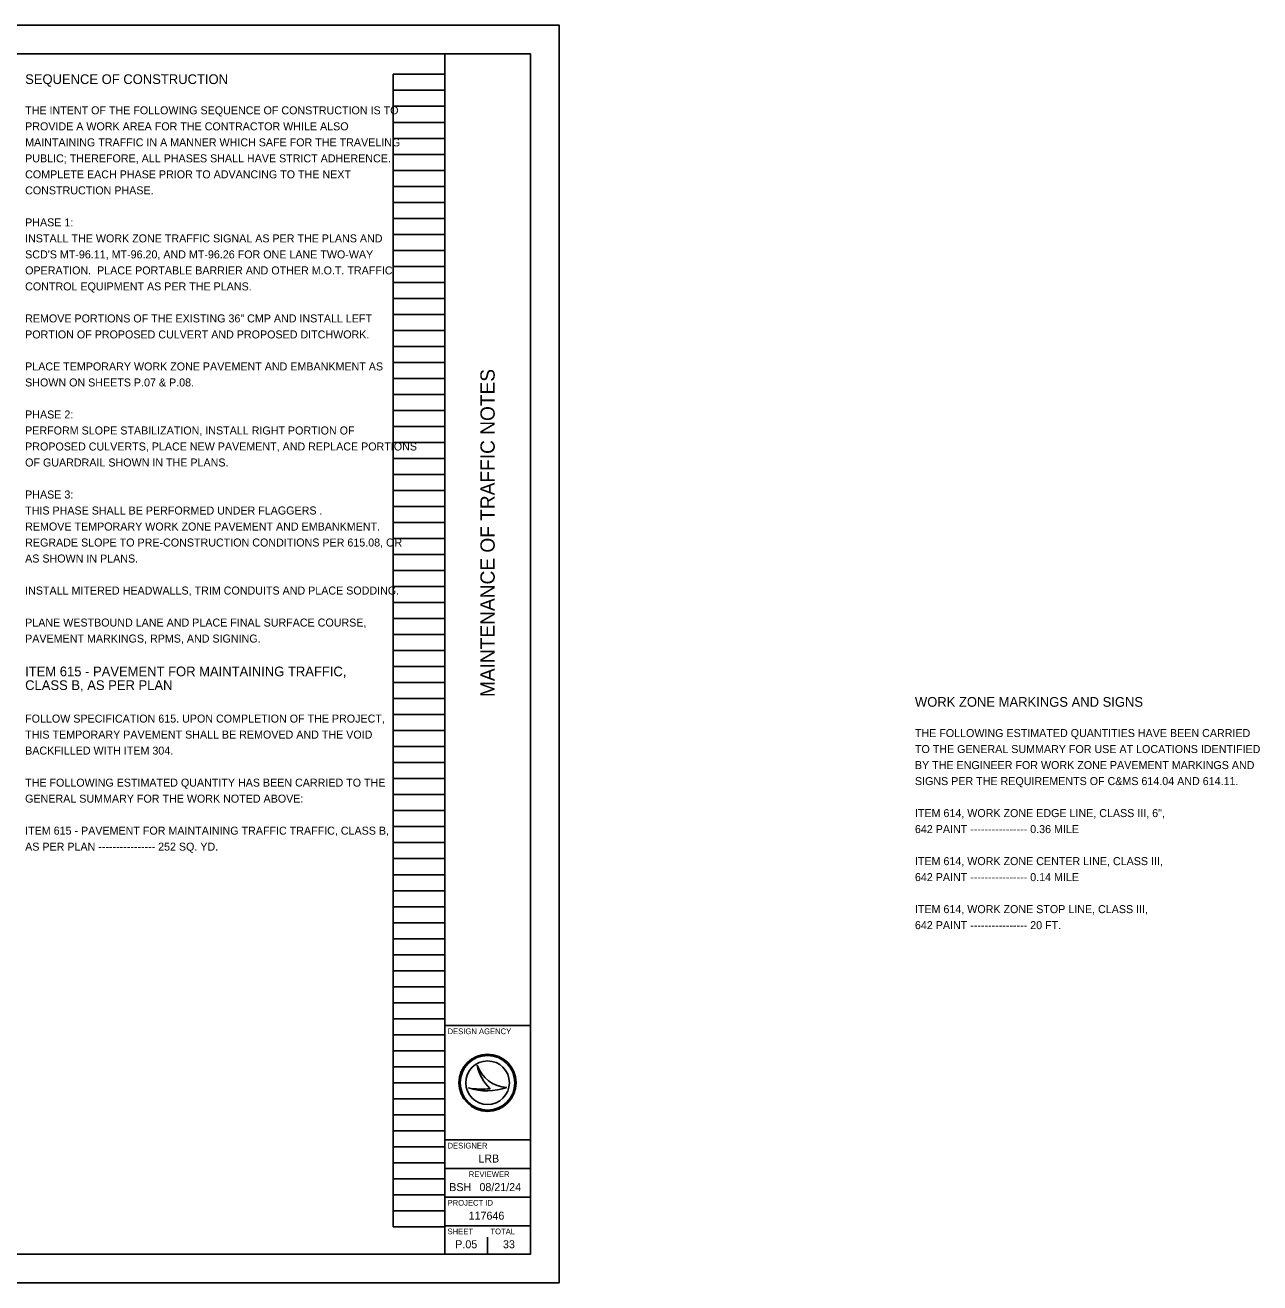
# Model space of a CAD drawing. Extents: x -7.5 to 46.3, y -5.1 to 34.9.
# Drawn here: x 24.66 to 46.26, y 0 to 22 of the extents above; entities that cross this region are included whole.
import ezdxf

# ---------------------------------------------------------------- set-up
doc = ezdxf.new("R2010")
doc.units = 0
for name, color, linetype in [('SH_Border', 7, 'Continuous'), ('SH_Cut_Line', 7, 'Continuous'), ('SH_Data', 7, 'Continuous'), ('SH_Text', 7, 'Continuous')]:
    doc.layers.add(name, color=color, linetype=linetype)

msp = doc.modelspace()

# ---------------------------------------------------------------- linework, layer by layer
at = {"layer": 'SH_Border'}
for p, q in [((32, 0.5), (32, 21.5)), ((32, 4.5), (33.5, 4.5)), ((32, 2.5), (33.5, 2.5)), ((32, 2), (33.5, 2)), ((32, 1.5), (33.5, 1.5)), ((32, 1), (33.5, 1))]:
    msp.add_line(p, q, dxfattribs=at)
msp.add_lwpolyline([(1.5, 21.5), (33.5, 21.5), (33.5, 0.5), (1.5, 0.5)], close=True, dxfattribs=at)
at = {"layer": 'SH_Cut_Line'}
msp.add_lwpolyline([(0, 0), (34, 0), (34, 22), (0, 22)], close=True, dxfattribs=at)
at = {"layer": 'SH_Data'}
for p, q in [((31.1, 0.98), (31.1, 21.14)), ((31.1, 21.14), (32, 21.14)), ((32, 0.98), (32, 21.14)), ((31.1, 20.86), (32, 20.86)), ((31.1, 20.58), (32, 20.58)), ((31.1, 20.3), (32, 20.3)), ((31.1, 20.02), (32, 20.02)), ((31.1, 19.74), (32, 19.74)), ((31.1, 19.46), (32, 19.46)), ((31.1, 19.18), (32, 19.18)), ((31.1, 18.9), (32, 18.9)), ((31.1, 18.62), (32, 18.62)), ((31.1, 18.34), (32, 18.34)), ((31.1, 18.06), (32, 18.06)), ((31.1, 17.78), (32, 17.78)), ((31.1, 17.5), (32, 17.5)), ((31.1, 17.22), (32, 17.22)), ((31.1, 16.94), (32, 16.94)), ((31.1, 16.66), (32, 16.66)), ((31.1, 16.38), (32, 16.38)), ((31.1, 16.1), (32, 16.1)), ((31.1, 15.82), (32, 15.82)), ((31.1, 15.54), (32, 15.54)), ((31.1, 15.26), (32, 15.26)), ((31.1, 14.98), (32, 14.98)), ((31.1, 14.7), (32, 14.7)), ((31.1, 14.42), (32, 14.42)), ((31.1, 14.14), (32, 14.14)), ((31.1, 13.86), (32, 13.86)), ((31.1, 13.58), (32, 13.58)), ((31.1, 13.3), (32, 13.3)), ((31.1, 13.02), (32, 13.02)), ((31.1, 12.74), (32, 12.74)), ((31.1, 12.46), (32, 12.46)), ((31.1, 12.18), (32, 12.18)), ((31.1, 11.9), (32, 11.9)), ((31.1, 11.62), (32, 11.62)), ((31.1, 11.34), (32, 11.34)), ((31.1, 11.06), (32, 11.06)), ((31.1, 10.78), (32, 10.78)), ((31.1, 10.5), (32, 10.5)), ((31.1, 10.22), (32, 10.22)), ((31.1, 9.94), (32, 9.94)), ((31.1, 9.66), (32, 9.66)), ((31.1, 9.38), (32, 9.38)), ((31.1, 9.1), (32, 9.1)), ((31.1, 8.82), (32, 8.82)), ((31.1, 8.54), (32, 8.54)), ((31.1, 8.26), (32, 8.26)), ((31.1, 7.98), (32, 7.98)), ((31.1, 7.7), (32, 7.7)), ((31.1, 7.42), (32, 7.42)), ((31.1, 7.14), (32, 7.14)), ((31.1, 6.86), (32, 6.86)), ((31.1, 6.58), (32, 6.58)), ((31.1, 6.3), (32, 6.3)), ((31.1, 6.02), (32, 6.02)), ((31.1, 5.74), (32, 5.74)), ((31.1, 5.46), (32, 5.46)), ((31.1, 5.18), (32, 5.18)), ((31.1, 4.9), (32, 4.9)), ((31.1, 4.62), (32, 4.62)), ((31.1, 4.34), (32, 4.34)), ((31.1, 4.06), (32, 4.06)), ((31.1, 3.78), (32, 3.78)), ((32.567, 3.81), (32.567, 3.81)), ((31.1, 3.5), (32, 3.5)), ((32.417, 3.41), (32.417, 3.41)), ((32.75, 3.5), (32.75, 3.5)), ((33.087, 3.419), (33.087, 3.419)), ((31.1, 3.22), (32, 3.22)), ((31.1, 2.94), (32, 2.94)), ((31.1, 2.66), (32, 2.66)), ((31.1, 2.38), (32, 2.38)), ((31.1, 2.1), (32, 2.1)), ((31.1, 1.82), (32, 1.82)), ((31.1, 1.54), (32, 1.54)), ((31.1, 1.26), (32, 1.26)), ((31.1, 0.98), (32, 0.98)), ((32.375, 0.675), (32.375, 0.675)), ((32.75, 0.5), (32.75, 0.8))]:
    msp.add_line(p, q, dxfattribs=at)
for radius in [0.5, 0.477, 0.477, 0.382]:
    msp.add_circle((32.75, 3.5), radius, dxfattribs=at)
for centre, radius, start, end in [((33.116, 3.998), 0.58, 198.9257, 198.9319), ((33.347, 3.97), 0.796, 191.6379, 191.6421), ((33.116, 3.998), 0.58, 198.9319, 267.1657), ((33.347, 3.97), 0.796, 191.6421, 226.0947), ((32.739, 4.37), 1.013, 251.4576, 290.0832), ((32.648, 4.654), 1.266, 259.4964, 259.4995), ((32.739, 4.37), 1.013, 251.4527, 251.4576), ((32.648, 4.654), 1.266, 259.4995, 276.6672)]:
    msp.add_arc(centre, radius, start, end, dxfattribs=at)

# ---------------------------------------------------------------- texts
msp.add_text('MAINTENANCE OF TRAFFIC NOTES', height=0.25, rotation=90, dxfattribs=at).set_placement((32.875, 10.247))
for s, height, p in [('DESIGN AGENCY', 0.1, (32.05, 4.35)), ('DESIGNER', 0.1, (32.05, 2.35)), ('LRB', 0.14, (32.589, 2.105)), ('REVIEWER', 0.1, (32.422, 1.85)), ('BSH', 0.14, (32.08, 1.605)), ('08/21/24', 0.14, (32.608, 1.605)), ('PROJECT ID', 0.1, (32.05, 1.35)), ('117646', 0.14, (32.419, 1.105)), ('SHEET', 0.1, (32.05, 0.85)), ('TOTAL', 0.1, (32.8, 0.85)), ('P.05', 0.14, (32.185, 0.605)), ('33', 0.14, (33.02, 0.605))]:
    msp.add_text(s, height=height, dxfattribs=at).set_placement(p)
at = {"layer": 'SH_Text'}
for s, height, p in [('SEQUENCE OF CONSTRUCTION', 0.17, (24.66, 20.97)), ('THE INTENT OF THE FOLLOWING SEQUENCE OF CONSTRUCTION IS TO ', 0.14, (24.66, 20.44)), ('PROVIDE A WORK AREA FOR THE CONTRACTOR WHILE ALSO ', 0.14, (24.66, 20.16)), ('MAINTAINING TRAFFIC IN A MANNER WHICH SAFE FOR THE TRAVELING ', 0.14, (24.66, 19.88)), ('PUBLIC; THEREFORE, ALL PHASES SHALL HAVE STRICT ADHERENCE. ', 0.14, (24.66, 19.6)), ('COMPLETE EACH PHASE PRIOR TO ADVANCING TO THE NEXT ', 0.14, (24.66, 19.32)), ('CONSTRUCTION PHASE.', 0.14, (24.66, 19.04)), ('PHASE 1:', 0.14, (24.66, 18.48)), ('INSTALL THE WORK ZONE TRAFFIC SIGNAL AS PER THE PLANS AND  ', 0.14, (24.66, 18.2)), ("SCD'S MT-96.11, MT-96.20, AND MT-96.26 FOR ONE LANE TWO-WAY ", 0.14, (24.66, 17.92)), ('OPERATION.  PLACE PORTABLE BARRIER AND OTHER M.O.T. TRAFFIC ', 0.14, (24.66, 17.64)), ('CONTROL EQUIPMENT AS PER THE PLANS.  ', 0.14, (24.66, 17.36)), ('REMOVE PORTIONS OF THE EXISTING 36" CMP AND INSTALL LEFT ', 0.14, (24.66, 16.8)), ('PORTION OF PROPOSED CULVERT AND PROPOSED DITCHWORK.  ', 0.14, (24.66, 16.52)), ('PLACE TEMPORARY WORK ZONE PAVEMENT AND EMBANKMENT AS ', 0.14, (24.66, 15.96)), ('SHOWN ON SHEETS P.07 & P.08.', 0.14, (24.66, 15.68)), ('PHASE 2:', 0.14, (24.66, 15.12)), ('PERFORM SLOPE STABILIZATION, INSTALL RIGHT PORTION OF ', 0.14, (24.66, 14.84)), ('PROPOSED CULVERTS, PLACE NEW PAVEMENT, AND REPLACE PORTIONS ', 0.14, (24.66, 14.56)), ('OF GUARDRAIL SHOWN IN THE PLANS.', 0.14, (24.66, 14.28)), ('PHASE 3:', 0.14, (24.66, 13.72)), ('THIS PHASE SHALL BE PERFORMED UNDER FLAGGERS .', 0.14, (24.66, 13.44)), ('REMOVE TEMPORARY WORK ZONE PAVEMENT AND EMBANKMENT.  ', 0.14, (24.66, 13.16)), ('REGRADE SLOPE TO PRE-CONSTRUCTION CONDITIONS PER 615.08, OR ', 0.14, (24.66, 12.88)), ('AS SHOWN IN PLANS.', 0.14, (24.66, 12.6)), ('INSTALL MITERED HEADWALLS, TRIM CONDUITS AND PLACE SODDING.', 0.14, (24.66, 12.04)), ('PLANE WESTBOUND LANE AND PLACE FINAL SURFACE COURSE,  ', 0.14, (24.66, 11.48)), ('PAVEMENT MARKINGS, RPMS, AND SIGNING.', 0.14, (24.66, 11.2)), ('ITEM 615 - PAVEMENT FOR MAINTAINING TRAFFIC, ', 0.17, (24.66, 10.61)), ('CLASS B, AS PER PLAN', 0.17, (24.66, 10.37)), ('WORK ZONE MARKINGS AND SIGNS', 0.17, (40.227, 10.077)), ('FOLLOW SPECIFICATION 615. UPON COMPLETION OF THE PROJECT, ', 0.14, (24.66, 9.8)), ('THE FOLLOWING ESTIMATED QUANTITIES HAVE BEEN CARRIED', 0.14, (40.227, 9.547)), ('THIS TEMPORARY PAVEMENT SHALL BE REMOVED AND THE VOID ', 0.14, (24.66, 9.52)), ('BACKFILLED WITH ITEM 304.', 0.14, (24.66, 9.24)), ('TO THE GENERAL SUMMARY FOR USE AT LOCATIONS IDENTIFIED', 0.14, (40.227, 9.267)), ('BY THE ENGINEER FOR WORK ZONE PAVEMENT MARKINGS AND', 0.14, (40.227, 8.987)), ('THE FOLLOWING ESTIMATED QUANTITY HAS BEEN CARRIED TO THE ', 0.14, (24.66, 8.68)), ('SIGNS PER THE REQUIREMENTS OF C&MS 614.04 AND 614.11.', 0.14, (40.227, 8.707)), ('GENERAL SUMMARY FOR THE WORK NOTED ABOVE:', 0.14, (24.66, 8.4)), ('ITEM 614, WORK ZONE EDGE LINE, CLASS III, 6",', 0.14, (40.227, 8.147)), ('ITEM 615 - PAVEMENT FOR MAINTAINING TRAFFIC TRAFFIC, CLASS B, ', 0.14, (24.66, 7.84)), ('642 PAINT ---------------- 0.36 MILE', 0.14, (40.227, 7.867)), ('AS PER PLAN ---------------- ', 0.14, (24.66, 7.56)), ('252 SQ. YD.', 0.14, (26.986, 7.56)), ('ITEM 614, WORK ZONE CENTER LINE, CLASS III, ', 0.14, (40.227, 7.307)), ('642 PAINT ---------------- 0.14 MILE', 0.14, (40.227, 7.027)), ('ITEM 614, WORK ZONE STOP LINE, CLASS III, ', 0.14, (40.227, 6.467)), ('642 PAINT ---------------- 20 FT.', 0.14, (40.227, 6.187))]:
    msp.add_text(s, height=height, dxfattribs=at).set_placement(p)

doc.saveas('drawing.dxf')
